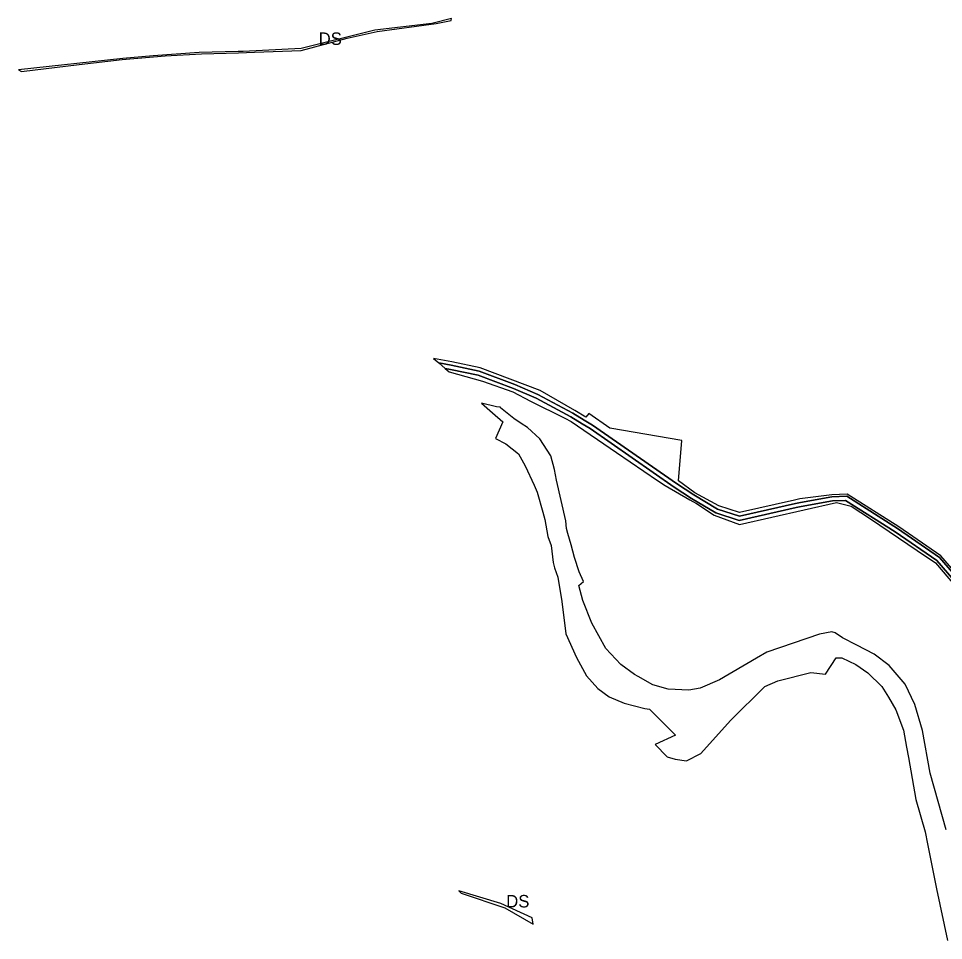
# Model space of a CAD drawing. Extents: x -477304 to -465641, y -1159113 to -1149285.
# Drawn here: x -477304 to -476638, y -1151089 to -1150424 of the extents above; entities that cross this region are included whole.
import ezdxf

# ---------------------------------------------------------------- set-up
doc = ezdxf.new("R2010")
doc.units = 0
doc.layers.add('14', color=7, linetype='Continuous')
doc.layers.add('35', color=7, linetype='Continuous')

msp = doc.modelspace()

# ---------------------------------------------------------------- linework, layer by layer
at = {"layer": '14'}
msp.add_line((-477001.23, -1150672.48), (-476996.59, -1150676.38), dxfattribs=at)
for points in [[(-476718.17, -1150768.82), (-476740.81, -1150772.88), (-476744.51, -1150773.62), (-476784.73, -1150782.82), (-476800.48, -1150777.74), (-476817.59, -1150767.49), (-476830.05, -1150759.42), (-476890.51, -1150717.23), (-476896.52, -1150713.7), (-476904.68, -1150708.72), (-476929.93, -1150695.16), (-476946.38, -1150688.01), (-476972.11, -1150678.48), (-476992.2, -1150674.14), (-477001.23, -1150672.48)], [(-476996.59, -1150676.38), (-476992.79, -1150677.08), (-476972.96, -1150681.36), (-476947.5, -1150690.79), (-476931.24, -1150697.86), (-476906.17, -1150711.32), (-476898.06, -1150716.27), (-476892.13, -1150719.76), (-476831.72, -1150761.91), (-476819.18, -1150770.03), (-476801.73, -1150780.49), (-476784.87, -1150785.93), (-476743.88, -1150776.55), (-476740.25, -1150775.83), (-476717.85, -1150771.81)], [(-476623.5, -1150832.43), (-476640.64, -1150812.58), (-476670.87, -1150791.66), (-476707.47, -1150768.46), (-476718.17, -1150768.82)], [(-476717.85, -1150771.81), (-476708.3, -1150771.49), (-476672.53, -1150794.16), (-476642.66, -1150814.82), (-476625.91, -1150834.23)]]:
    msp.add_lwpolyline(points, dxfattribs=at)
at = {"layer": '35'}
for p, q in [((-477003.05, -1150427.99), (-476992.29, -1150425.74)), ((-476992.29, -1150425.74), (-476992.15, -1150424.35)), ((-477100.24, -1150447.41), (-477067.15, -1150438.56)), ((-477260.08, -1150457.59), (-477229.1, -1150453.81)), ((-477229.1, -1150453.81), (-477198.32, -1150451.36)), ((-477134.02, -1150448.5), (-477100.24, -1150447.41)), ((-477301.68, -1150462.42), (-477260.08, -1150457.59)), ((-477005.03, -1150669.28), (-477001.23, -1150672.48)), ((-476996.59, -1150676.38), (-476993.72, -1150678.8)), ((-476993.72, -1150678.8), (-476969.74, -1150685.67)), ((-476969.74, -1150685.67), (-476947.81, -1150693.34)), ((-476947.81, -1150693.34), (-476935.25, -1150699.92)), ((-476903.4, -1150706.62), (-476928.23, -1150692.23)), ((-476935.25, -1150699.92), (-476910.54, -1150712.32)), ((-476959.61, -1150703.97), (-476970.4, -1150701.41)), ((-476970.4, -1150701.41), (-476962.45, -1150708.29)), ((-476895.26, -1150711.59), (-476903.4, -1150706.62)), ((-476910.54, -1150712.32), (-476905.87, -1150714.66)), ((-476893.2, -1150708.77), (-476895.26, -1150711.59)), ((-476877.98, -1150719.54), (-476893.2, -1150708.77)), ((-476905.87, -1150714.66), (-476873.3, -1150736.95)), ((-476826.28, -1150728.25), (-476877.98, -1150719.54)), ((-476953.05, -1150730.63), (-476943.85, -1150738)), ((-476920.59, -1150739.4), (-476928.54, -1150727.23)), ((-476828.58, -1150757.45), (-476826.28, -1150728.25)), ((-476909.73, -1150786.1), (-476916.59, -1150756.98)), ((-476932.64, -1150760.43), (-476930.31, -1150765.52)), ((-476838.16, -1150760.67), (-476820.44, -1150771)), ((-476820.44, -1150771), (-476815.66, -1150773.79)), ((-476784.71, -1150788.92), (-476714.91, -1150772.91)), ((-476815.66, -1150773.79), (-476803.01, -1150782.24)), ((-476784.62, -1150780.27), (-476799.54, -1150775.46)), ((-476803.01, -1150782.24), (-476784.71, -1150788.92)), ((-476690.5, -1150784.87), (-476656.85, -1150807.48)), ((-476906.04, -1150803.45), (-476908.24, -1150795.28)), ((-476920.38, -1150804.01), (-476918.78, -1150816.14)), ((-476903.43, -1150812.71), (-476906.04, -1150803.45)), ((-476900.12, -1150822.94), (-476903.43, -1150812.71)), ((-476656.85, -1150807.48), (-476643.54, -1150816.44)), ((-476622.38, -1150831.6), (-476639.7, -1150811.53)), ((-476918.78, -1150816.14), (-476917.88, -1150820.05)), ((-476917.88, -1150820.05), (-476915.58, -1150826.75)), ((-476643.54, -1150816.44), (-476625.93, -1150837.46)), ((-476897.12, -1150829.92), (-476900.12, -1150822.94)), ((-476900.38, -1150832.75), (-476897.12, -1150829.92)), ((-476897.43, -1150843.71), (-476900.38, -1150832.75)), ((-476891.08, -1150860.02), (-476897.43, -1150843.71)), ((-476880.96, -1150878.2), (-476891.08, -1150860.02)), ((-476718.33, -1150866.09), (-476727.21, -1150867.95)), ((-476715.76, -1150866.79), (-476718.33, -1150866.09)), ((-476909.69, -1150867.49), (-476902.09, -1150884.73)), ((-476710.47, -1150870.46), (-476715.76, -1150866.79)), ((-476722.71, -1150896.56), (-476715.15, -1150884.99)), ((-476715.15, -1150884.99), (-476710.94, -1150884.82)), ((-476710.94, -1150884.82), (-476701.07, -1150889.58)), ((-476857.63, -1150898.32), (-476860.21, -1150896.78)), ((-476766.39, -1150905.56), (-476757.04, -1150901.57)), ((-476682.32, -1150905.61), (-476677.36, -1150913.17)), ((-476852.85, -1150921.47), (-476849.62, -1150921.87)), ((-476849.62, -1150921.87), (-476830.86, -1150940.55)), ((-476666.61, -1150937.08), (-476664.44, -1150949.33)), ((-476664.44, -1150949.33), (-476663.13, -1150956.76)), ((-476663.13, -1150956.76), (-476657.66, -1150986.89)), ((-476956.58, -1151061.94), (-476986.85, -1151052.63)), ((-476986.85, -1151052.63), (-476985.03, -1151054.52)), ((-476985.03, -1151054.52), (-476953.75, -1151065.09)), ((-476953.75, -1151065.09), (-476933.25, -1151076.77))]:
    msp.add_line(p, q, dxfattribs=at)
for points in [[(-476992.15, -1150424.35), (-477006.26, -1150428.03), (-477047.23, -1150432.66), (-477100.32, -1150445.88), (-477142.09, -1150448.11), (-477145.67, -1150448.19), (-477173.74, -1150448.82), (-477206.9, -1150451.29), (-477228.71, -1150453.2), (-477303.83, -1150461.3), (-477301.68, -1150462.42)], [(-477067.15, -1150438.56), (-477045.7, -1150433.75), (-477003.05, -1150427.99)], [(-477198.32, -1150451.36), (-477172.14, -1150449.74), (-477145.42, -1150449.13), (-477134.02, -1150448.5)], [(-476928.23, -1150692.23), (-476971.42, -1150676.11), (-476991.72, -1150671.73), (-477005.03, -1150669.28)], [(-477001.23, -1150672.48), (-476992.2, -1150674.14), (-476972.11, -1150678.48), (-476946.38, -1150688.01), (-476929.93, -1150695.16), (-476904.68, -1150708.72), (-476896.52, -1150713.7), (-476890.51, -1150717.23), (-476830.05, -1150759.42), (-476817.59, -1150767.49), (-476800.48, -1150777.74), (-476784.73, -1150782.82), (-476744.51, -1150773.62), (-476740.81, -1150772.88), (-476718.17, -1150768.82)], [(-476717.85, -1150771.81), (-476740.25, -1150775.83), (-476743.88, -1150776.55), (-476784.87, -1150785.93), (-476801.73, -1150780.49), (-476819.18, -1150770.03), (-476831.72, -1150761.91), (-476892.13, -1150719.76), (-476898.06, -1150716.27), (-476906.17, -1150711.32), (-476931.24, -1150697.86), (-476947.5, -1150690.79), (-476972.96, -1150681.36), (-476992.79, -1150677.08), (-476996.59, -1150676.38)], [(-476956.86, -1150704.86), (-476956.79, -1150704.26), (-476959.61, -1150703.97)], [(-476941.96, -1150716), (-476947.22, -1150712.5), (-476956.86, -1150704.86)], [(-476962.45, -1150708.29), (-476955.21, -1150715.01), (-476960.42, -1150726.85), (-476953.05, -1150730.63)], [(-476928.54, -1150727.23), (-476937.33, -1150719.07), (-476941.96, -1150716)], [(-476943.85, -1150738), (-476938.96, -1150746.66), (-476932.64, -1150760.43)], [(-476916.59, -1150756.98), (-476917.82, -1150749.26), (-476920.59, -1150739.4)], [(-476873.3, -1150736.95), (-476843.65, -1150757.23), (-476838.16, -1150760.67)], [(-476799.54, -1150775.46), (-476816.98, -1150765.98), (-476828.58, -1150757.45)], [(-476930.31, -1150765.52), (-476926.34, -1150779.9), (-476924.83, -1150785.14), (-476922.63, -1150797.6), (-476920.38, -1150804.01)], [(-476707.09, -1150767.05), (-476718.25, -1150767.43), (-476741.17, -1150770.45), (-476745.02, -1150771.21), (-476784.62, -1150780.27)], [(-476718.17, -1150768.82), (-476707.47, -1150768.46), (-476670.87, -1150791.66), (-476640.64, -1150812.58), (-476623.5, -1150832.43)], [(-476625.91, -1150834.23), (-476642.66, -1150814.82), (-476672.53, -1150794.16), (-476708.3, -1150771.49), (-476717.85, -1150771.81)], [(-476714.91, -1150772.91), (-476704.24, -1150775.61), (-476690.5, -1150784.87)], [(-476639.7, -1150811.53), (-476670.1, -1150790.5), (-476707.09, -1150767.05)], [(-476908.24, -1150795.28), (-476909.2, -1150791.7), (-476909.73, -1150786.1)], [(-476915.58, -1150826.75), (-476912.58, -1150844.37), (-476909.69, -1150867.49)], [(-476727.21, -1150867.95), (-476764.96, -1150880.77), (-476772.43, -1150885.13)], [(-476687.72, -1150882.23), (-476700.17, -1150875.7), (-476710.47, -1150870.46)], [(-476860.21, -1150896.78), (-476870.06, -1150889.67), (-476880.96, -1150878.2)], [(-476902.09, -1150884.73), (-476894.95, -1150897.87), (-476886.76, -1150906.99), (-476878.63, -1150912.91)], [(-476772.43, -1150885.13), (-476799.02, -1150900.66), (-476813.03, -1150906.78), (-476821.28, -1150908.29), (-476836.19, -1150907.54)], [(-476636, -1151008.86), (-476647.34, -1150968.02), (-476653.08, -1150937.24), (-476658.4, -1150918.61), (-476665.53, -1150903.88), (-476677.04, -1150890.53), (-476687.72, -1150882.23)], [(-476701.07, -1150889.58), (-476692.42, -1150895.81), (-476682.32, -1150905.61)], [(-476836.19, -1150907.54), (-476847.15, -1150904.35), (-476857.63, -1150898.32)], [(-476757.04, -1150901.57), (-476733.33, -1150895.54), (-476722.71, -1150896.56)], [(-476822.87, -1150959.17), (-476812.56, -1150953.81), (-476791.13, -1150930.01), (-476766.39, -1150905.56)], [(-476878.63, -1150912.91), (-476867.73, -1150917.51), (-476852.85, -1150921.47)], [(-476677.36, -1150913.17), (-476672.17, -1150922.38), (-476666.61, -1150937.08)], [(-476830.86, -1150940.55), (-476845.5, -1150947.38), (-476836.72, -1150956.13)], [(-476836.72, -1150956.13), (-476831.04, -1150957.93), (-476822.87, -1150959.17)], [(-476657.66, -1150986.89), (-476650.96, -1151010.15), (-476649.25, -1151018.99)], [(-476649.25, -1151018.99), (-476643, -1151051.19), (-476634.92, -1151088.51)], [(-476933.25, -1151076.77), (-476934.06, -1151072.16), (-476956.58, -1151061.94)]]:
    msp.add_lwpolyline(points, dxfattribs=at)

# ---------------------------------------------------------------- texts
for p in [(-477087.75, -1150443.39), (-476952.7, -1151064.7)]:
    msp.add_text('DS', height=9, dxfattribs=at).set_placement(p)

doc.saveas('drawing.dxf')
